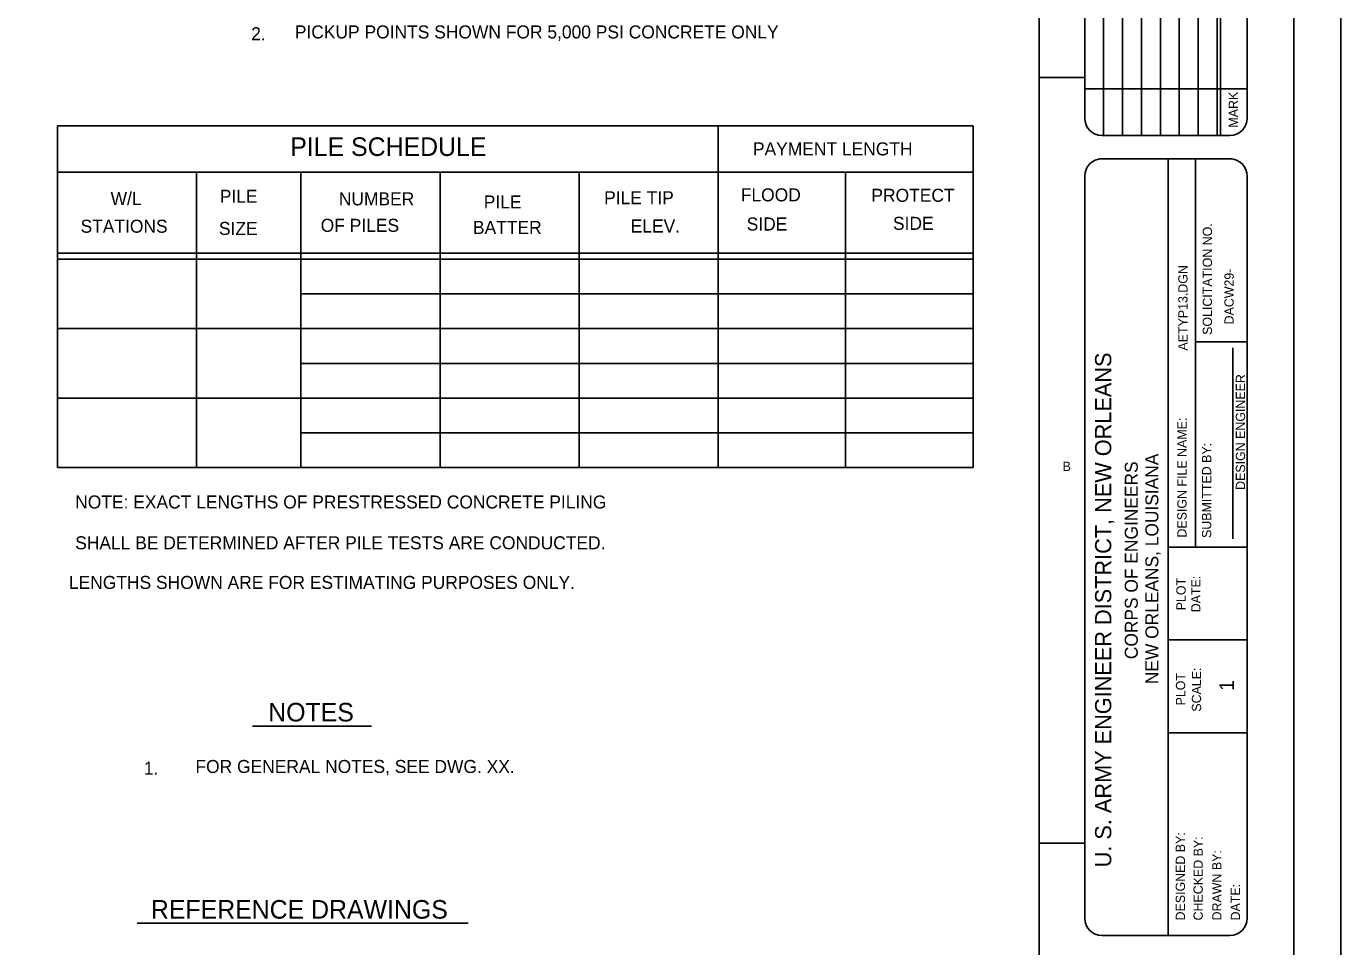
# Model space of a CAD drawing. Extents: x 22369.62 to 22373.29, y 22369.62 to 22372.46.
# Drawn here: x 22372.107 to 22373.288, y 22370.257 to 22371.084 of the extents above; entities that cross this region are included whole.
import ezdxf

# ---------------------------------------------------------------- set-up
doc = ezdxf.new("R2010")
doc.units = 0
for name, color, linetype in [('Level 1', 7, 'Continuous'), ('Level 10', 7, 'Continuous'), ('Level 2', 7, 'Continuous'), ('Level 4', 7, 'Continuous'), ('Level 7', 7, 'Continuous'), ('Level 9', 7, 'Continuous'), ('S-ANNO-DIMS', 7, 'Continuous')]:
    doc.layers.add(name, color=color, linetype=linetype)

msp = doc.modelspace()

# ---------------------------------------------------------------- linework, layer by layer
at = {"layer": 'Level 1'}
for p, q in [((22373.075, 22372.2363), (22373.075, 22370.9863)), ((22373.092, 22372.2363), (22373.092, 22370.9863)), ((22373.109, 22372.2363), (22373.109, 22370.9863)), ((22373.126, 22372.2363), (22373.126, 22370.9863)), ((22373.143, 22372.2363), (22373.143, 22370.9863)), ((22373.16, 22372.2363), (22373.16, 22370.9863)), ((22373.177, 22372.2363), (22373.177, 22370.9863)), ((22373.18, 22372.2363), (22373.18, 22370.9863)), ((22373.1884, 22370.9863), (22373.0736, 22370.9863)), ((22373.19, 22370.9653), (22373.071, 22370.9653)), ((22373.133, 22370.9653), (22373.133, 22370.2673))]:
    msp.add_line(p, q, dxfattribs=at)
msp.add_lwpolyline([(22369.6213, 22372.4553), (22373.288, 22372.4553), (22373.288, 22369.6213), (22369.6213, 22369.6213)], close=True, dxfattribs=at)
for points in [[(22373.058, 22371.0019), (22373.058, 22372.2207)], [(22373.204, 22371.0019), (22373.204, 22372.2207)], [(22373.1884, 22370.9653), (22373.0736, 22370.9653)], [(22373.058, 22370.2829), (22373.058, 22370.9497)], [(22373.204, 22370.2829), (22373.204, 22370.9497)], [(22373.0736, 22370.2673), (22373.1884, 22370.2673)]]:
    msp.add_lwpolyline(points, dxfattribs=at)
for centre, start, end in [((22373.0736, 22371.0019), 180, 270), ((22373.1884, 22371.0019), 270, 0), ((22373.0736, 22370.9497), 90, 180), ((22373.1884, 22370.9497), 0, 90), ((22373.0736, 22370.2829), 180, 270), ((22373.1884, 22370.2829), 270, 0)]:
    msp.add_arc(centre, 0.0156, start, end, dxfattribs=at)
at = {"layer": 'Level 10'}
for p, q in [((22373.017, 22371.0383), (22373.058, 22371.0383)), ((22373.017, 22370.3503), (22373.058, 22370.3503))]:
    msp.add_line(p, q, dxfattribs=at)
at = {"layer": 'Level 2'}
for p, q in [((22373.1576, 22370.9653), (22373.1576, 22370.6163)), ((22372.1353, 22370.9533), (22372.9579, 22370.9533)), ((22372.1353, 22370.8804), (22372.9579, 22370.8804)), ((22372.1353, 22370.8752), (22372.9579, 22370.8752)), ((22372.1353, 22370.8127), (22372.9579, 22370.8127)), ((22373.204, 22370.801), (22373.1576, 22370.801)), ((22373.191, 22370.6239), (22373.191, 22370.7956)), ((22372.1353, 22370.7502), (22372.9579, 22370.7502)), ((22373.204, 22370.6163), (22373.133, 22370.6163)), ((22373.204, 22370.533), (22373.133, 22370.533)), ((22373.204, 22370.4496), (22373.133, 22370.4496))]:
    msp.add_line(p, q, dxfattribs=at)
at = {"layer": 'Level 7'}
for p, q in [((22373.204, 22371.0283), (22373.058, 22371.0283)), ((22372.1353, 22370.6878), (22372.1353, 22370.9949)), ((22372.1353, 22370.9949), (22372.9579, 22370.9949)), ((22372.9579, 22370.6878), (22372.9579, 22370.9949)), ((22372.1353, 22370.6878), (22372.9579, 22370.6878)), ((22372.3105, 22370.4555), (22372.4173, 22370.4555)), ((22372.2069, 22370.2783), (22372.5043, 22370.2783))]:
    msp.add_line(p, q, dxfattribs=at)
at = {"layer": 'Level 9'}
msp.add_line((22373.246, 22369.6633), (22373.246, 22372.4133), dxfattribs=at)
msp.add_lwpolyline([(22373.017, 22369.6633), (22373.017, 22372.4133)], dxfattribs=at)
at = {"layer": 'S-ANNO-DIMS'}
for p, q in [((22372.7288, 22370.6878), (22372.7288, 22370.9949)), ((22372.2602, 22370.6878), (22372.2602, 22370.9533)), ((22372.354, 22370.6878), (22372.354, 22370.9533)), ((22372.4789, 22370.6878), (22372.4789, 22370.9533)), ((22372.6039, 22370.6878), (22372.6039, 22370.9533)), ((22372.8433, 22370.9533), (22372.8433, 22370.6878)), ((22372.354, 22370.8439), (22372.9579, 22370.8439)), ((22372.354, 22370.7815), (22372.9579, 22370.7815)), ((22372.354, 22370.719), (22372.9579, 22370.719))]:
    msp.add_line(p, q, dxfattribs=at)

# ---------------------------------------------------------------- texts
at = {"layer": 'Level 1'}
for s, height, p in [('MARK', 0.00833, (22373.1957, 22370.9934)), ('SOLICITATION NO.', 0.008333, (22373.1724, 22370.8071)), ('AETYP13.DGN', 0.008333, (22373.1504, 22370.793)), ('U. S. ARMY ENGINEER DISTRICT, NEW ORLEANS', 0.014583, (22373.0819, 22370.3286)), ('DESIGN ENGINEER', 0.008333, (22373.2021, 22370.6678)), ('DESIGN FILE NAME:', 0.008333, (22373.1495, 22370.625)), ('SUBMITTED BY:', 0.008333, (22373.1717, 22370.6246)), ('PLOT', 0.00833, (22373.1487, 22370.5596)), ('DATE:', 0.00833, (22373.162, 22370.5578)), ('PLOT', 0.00833, (22373.1483, 22370.4741)), ('SCALE:', 0.00833, (22373.1626, 22370.4685)), ('DESIGNED BY:', 0.008333, (22373.1481, 22370.2809)), ('CHECKED BY:', 0.008333, (22373.1641, 22370.2809)), ('DRAWN BY:', 0.00833, (22373.1809, 22370.2809)), ('DATE:', 0.00833, (22373.1976, 22370.2809))]:
    msp.add_text(s, height=height, rotation=90, dxfattribs=at).set_placement(p)
msp.add_text('B', height=0.00833, dxfattribs=at).set_placement((22373.0382, 22370.6848))
at = {"layer": 'Level 10'}
for s, height, p in [('PILE SCHEDULE', 0.016698, (22372.3444, 22370.9679)), ('NOTES', 0.0167, (22372.3246, 22370.4597)), ('REFERENCE DRAWINGS', 0.016698, (22372.2192, 22370.2825))]:
    msp.add_text(s, height=height, dxfattribs=at).set_placement(p)
at = {"layer": 'Level 4'}
for s, height, p in [('2.', 0.0117, (22372.3093, 22371.0719)), ('PICKUP POINTS SHOWN FOR 5,000 PSI CONCRETE ONLY', 0.011698, (22372.3485, 22371.0735)), ('PAYMENT LENGTH', 0.011698, (22372.76, 22370.9684)), ('W/L', 0.0117, (22372.183, 22370.9238)), ('PILE', 0.0117, (22372.2811, 22370.9258)), ('NUMBER', 0.0117, (22372.388, 22370.9235)), ('PILE TIP', 0.0117, (22372.6263, 22370.9245)), ('FLOOD', 0.0117, (22372.7491, 22370.9271)), ('PROTECT', 0.0117, (22372.8664, 22370.9267)), ('PILE', 0.0117, (22372.5182, 22370.9207)), ('STATIONS', 0.0117, (22372.156, 22370.8989)), ('OF PILES', 0.0117, (22372.3717, 22370.8997)), ('ELEV.', 0.0117, (22372.6502, 22370.8991)), ('SIDE', 0.0117, (22372.7544, 22370.9009)), ('SIDE', 0.0117, (22372.8858, 22370.9015)), ('SIZE', 0.0117, (22372.2803, 22370.8969)), ('BATTER', 0.0117, (22372.5085, 22370.8978)), ('NOTE: EXACT LENGTHS OF PRESTRESSED CONCRETE PILING', 0.011698, (22372.1512, 22370.6511)), ('SHALL BE DETERMINED AFTER PILE TESTS ARE CONDUCTED. ', 0.011698, (22372.1512, 22370.6144)), (' LENGTHS SHOWN ARE FOR ESTIMATING PURPOSES ONLY.', 0.011698, (22372.1412, 22370.5788)), ('1.', 0.0117, (22372.2129, 22370.4119)), ('FOR GENERAL NOTES, SEE DWG. XX.', 0.011698, (22372.2592, 22370.4134))]:
    msp.add_text(s, height=height, dxfattribs=at).set_placement(p)
at = {"layer": 'Level 7'}
for s, height, p in [('DACW29-', 0.00833, (22373.1919, 22370.8165)), ('NEW ORLEANS, LOUISIANA', 0.011667, (22373.1242, 22370.4932)), ('CORPS OF ENGINEERS', 0.011667, (22373.1057, 22370.5157)), ('1', 0.013, (22373.192, 22370.4872))]:
    msp.add_text(s, height=height, rotation=90, dxfattribs=at).set_placement(p)

doc.saveas('drawing.dxf')
